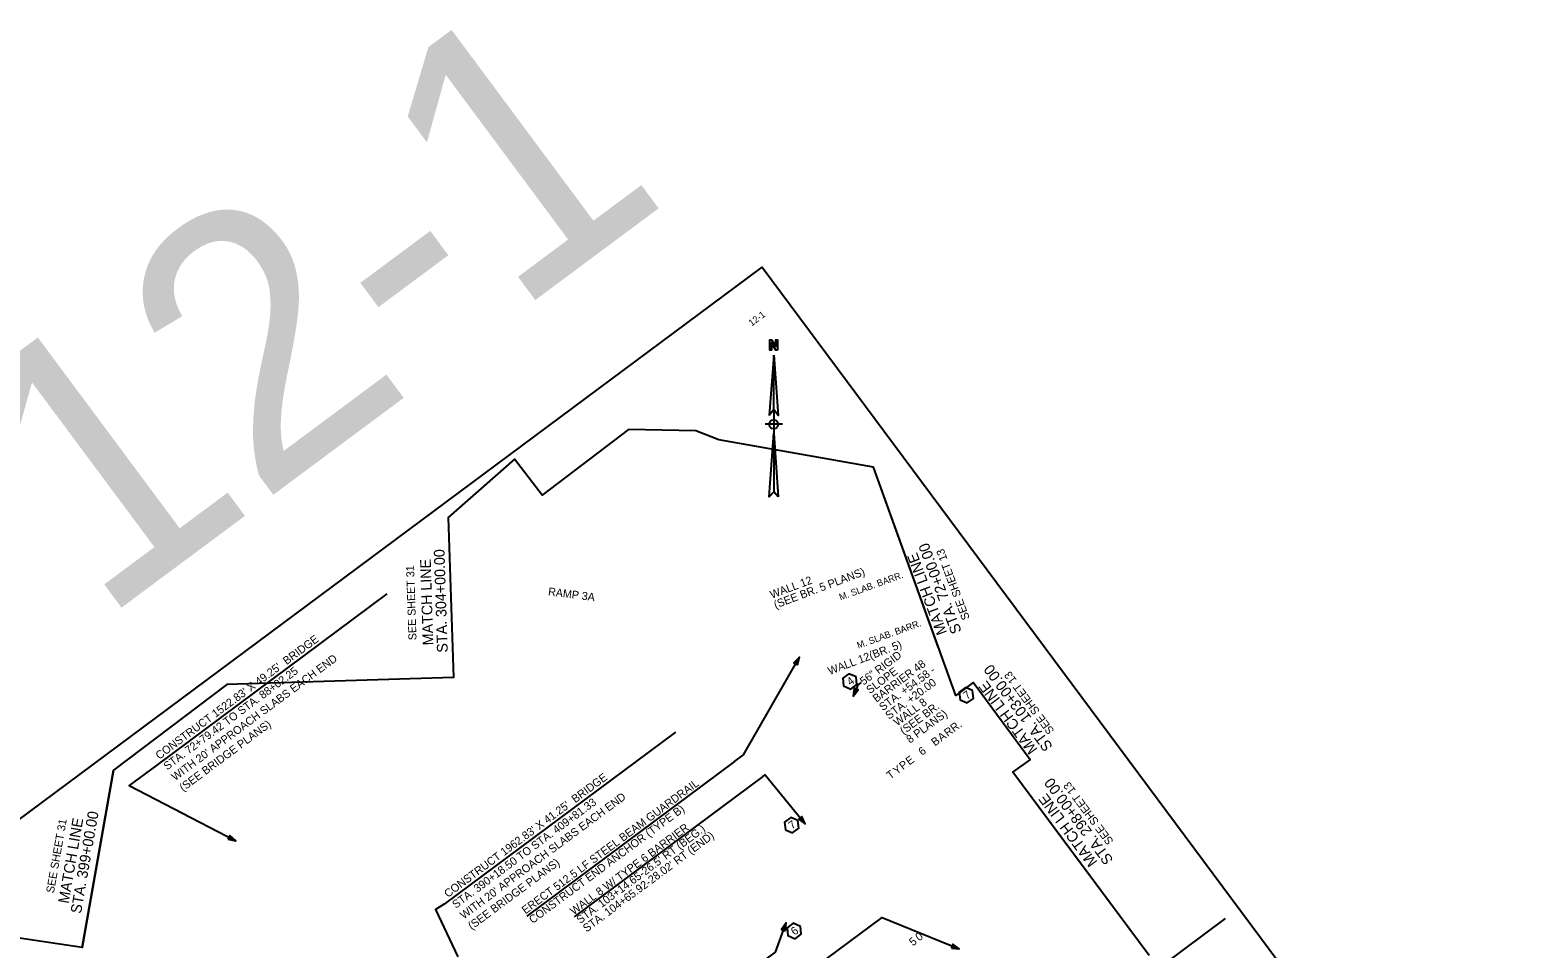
# Model space of a CAD drawing. Extents: x 1609621 to 1611756, y 1093008 to 1094970.
# Drawn here: x 1610636 to 1611756, y 1094282 to 1094970 of the extents above; entities that cross this region are included whole.
import ezdxf

# ---------------------------------------------------------------- set-up
doc = ezdxf.new("R2010")
doc.units = 0
for name, color, linetype in [('Level 1', 7, 'Continuous'), ('Level 2', 7, 'Continuous'), ('Plan_Clip', 7, 'Continuous'), ('RD_PD_GR_TX', 7, 'Continuous'), ('RD_SHT_MatchLine', 7, 'Continuous'), ('RD_SHT_Misc1', 7, 'Continuous'), ('RD_SHT_TX', 7, 'Continuous'), ('RD_TX_Bridge', 7, 'Continuous'), ('RD_TX_RoadID', 7, 'Continuous')]:
    doc.layers.add(name, color=color, linetype=linetype)

msp = doc.modelspace()

# ---------------------------------------------------------------- linework, layer by layer
at = {"layer": 'Level 1'}
for p, q in [((1611193.9, 1094726.3), (1611190.5, 1094681)), ((1611193.9, 1094685.6), (1611190.5, 1094681)), ((1611193.9, 1094685.6), (1611193.9, 1094667.8)), ((1611200.4, 1094674.4), (1611187.4, 1094674.4)), ((1611193.9, 1094667.8), (1611197.3, 1094620)), ((1611197.3, 1094620), (1611193.9, 1094623.8))]:
    msp.add_line(p, q, dxfattribs=at)
msp.add_lwpolyline([(1611196.8, 1094730.1), (1611195.6, 1094730.1), (1611192.2, 1094735.6), (1611192.2, 1094734.8), (1611192.2, 1094730.1), (1611190.9, 1094730.1), (1611190.9, 1094737.7), (1611192.2, 1094737.7), (1611195.6, 1094732.7), (1611195.6, 1094733.1), (1611195.6, 1094737.7), (1611196.8, 1094737.7), (1611196.8, 1094730.1)], dxfattribs=at)
for points in [[(1611193.9, 1094726.3), (1611197.3, 1094681), (1611193.9, 1094685.6)], [(1611193.9, 1094667.8), (1611193.9, 1094623.8), (1611190.5, 1094620)]]:
    msp.add_lwpolyline(points, close=True, dxfattribs=at)
msp.add_circle((1611193.9, 1094674.4), 3.45, dxfattribs=at)
at = {"layer": 'Level 2'}
msp.add_lwpolyline([(1609840.9, 1093793), (1611185.2, 1094792.2), (1611755.8, 1094024.6), (1610411.6, 1093025.3)], close=True, dxfattribs=at)
at = {"layer": 'Plan_Clip'}
msp.add_lwpolyline([(1611475.5, 1094276), (1611373.3, 1094413.5), (1611386.3, 1094422.9), (1611343.4, 1094480.7), (1611330.5, 1094471.1), (1611268.7, 1094642.2), (1611152.7, 1094662.8), (1611135.4, 1094669.5), (1611085, 1094670.6), (1611020.3, 1094621.2), (1610999.6, 1094648.3), (1610949.9, 1094604.4), (1610953.9, 1094484.5), (1610783.9, 1094479.2), (1610698.8, 1094415.1), (1610675.5, 1094282.2), (1610541, 1094302.1)], dxfattribs=at)
msp.add_lwpolyline([(1611475.5, 1094276), (1611373.3, 1094413.5), (1611386.3, 1094422.9), (1611343.4, 1094480.7), (1611330.5, 1094471.1), (1611268.7, 1094642.2), (1611152.7, 1094662.8), (1611135.4, 1094669.5), (1611085, 1094670.6), (1611020.3, 1094621.2), (1610999.6, 1094648.3), (1610949.9, 1094604.4), (1610953.9, 1094484.5), (1610783.9, 1094479.2), (1610698.8, 1094415.1), (1610675.5, 1094282.2), (1610541, 1094302.1)], dxfattribs=at)
at = {"layer": 'RD_PD_GR_TX'}
msp.add_line((1611164.4, 1094421.5), (1611008.7, 1094305.7), dxfattribs=at)
msp.add_lwpolyline([(1611164.4, 1094421.5), (1611171.3, 1094426.6), (1611213.2, 1094499.8)], dxfattribs=at)
msp.add_lwpolyline([(1611211.7, 1094494), (1611213.2, 1094499.8), (1611209, 1094495.6)], close=True, dxfattribs=at)
at = {"layer": 'RD_SHT_MatchLine'}
for p, q in [((1611317.5, 1094506.9), (1611268.7, 1094642.2)), ((1610949.9, 1094604.4), (1610953.9, 1094484.5)), ((1610675.5, 1094282.2), (1610698.8, 1094415.1))]:
    msp.add_line(p, q, dxfattribs=at)
for points in [[(1611386.3, 1094422.9), (1611343.4, 1094480.7)], [(1611475.5, 1094276), (1611410.8, 1094363.1), (1611373.3, 1094413.5)]]:
    msp.add_lwpolyline(points, dxfattribs=at)
at = {"layer": 'RD_SHT_TX'}
for p, q in [((1611185.7, 1094410.3), (1611044.4, 1094305.2)), ((1611532.4, 1094303.8), (1611430.1, 1094227.7))]:
    msp.add_line(p, q, dxfattribs=at)
for points in [[(1611255.7, 1094485.1), (1611250.3, 1094487.4), (1611245.7, 1094484), (1611246.3, 1094478.2), (1611251.7, 1094475.9), (1611256.3, 1094479.4)], [(1611254.3, 1094476.5), (1611253.5, 1094470.5), (1611257.2, 1094475.2)], [(1611343, 1094474.7), (1611337.7, 1094477), (1611333, 1094473.5), (1611333.7, 1094467.8), (1611339, 1094465.5), (1611343.7, 1094468.9)], [(1611212, 1094377.4), (1611206.7, 1094379.7), (1611202, 1094376.2), (1611202.7, 1094370.4), (1611208, 1094368.1), (1611212.7, 1094371.6)], [(1611212.6, 1094378.4), (1611217.5, 1094374.9), (1611215, 1094380.3)], [(1611202.7, 1094294.7), (1611203.2, 1094300.7), (1611199.8, 1094295.7)], [(1611213.9, 1094297.9), (1611208.6, 1094300.3), (1611203.9, 1094296.8), (1611204.6, 1094291), (1611209.9, 1094288.7), (1611214.6, 1094292.2)]]:
    msp.add_lwpolyline(points, close=True, dxfattribs=at)
for points in [[(1611259.5, 1094480.8), (1611257.1, 1094479.1), (1611253.5, 1094470.5)], [(1611185.7, 1094410.3), (1611187.4, 1094411.5), (1611217.5, 1094374.9)], [(1611187.4, 1094272.8), (1611195.3, 1094278.7), (1611203.2, 1094300.7)]]:
    msp.add_lwpolyline(points, dxfattribs=at)
at = {"layer": 'RD_TX_Bridge'}
for p, q in [((1610903.8, 1094547.2), (1610730.3, 1094418.2)), ((1611120.2, 1094443.5), (1610946.8, 1094314.6))]:
    msp.add_line(p, q, dxfattribs=at)
for points in [[(1610730.3, 1094418.2), (1610710.6, 1094403.5), (1610790.5, 1094362.1)], [(1610946.8, 1094314.6), (1610940.4, 1094310.5), (1610957.1, 1094275.1)], [(1611109.4, 1094181.4), (1611275.2, 1094304.6), (1611333, 1094281)]]:
    msp.add_lwpolyline(points, dxfattribs=at)
for points in [[(1610784.7, 1094363.4), (1610790.5, 1094362.1), (1610786.1, 1094366.1)], [(1611327.1, 1094281.7), (1611333, 1094281), (1611328.3, 1094284.6)]]:
    msp.add_lwpolyline(points, close=True, dxfattribs=at)

# ---------------------------------------------------------------- texts
at = {"layer": 'RD_PD_GR_TX'}
for s, p in [('ERECT 512.5 LF STEEL BEAM GUARDRAIL', (1611007.8, 1094306.9)), ('CONSTRUCT END ANCHOR (TYPE B)', (1611013.2, 1094299.7))]:
    msp.add_text(s, height=6, rotation=36.6272, dxfattribs=at).set_placement(p)
at = {"layer": 'RD_SHT_MatchLine'}
for s, height, rotation, p in [('STA. 304+00.00', 8, 91.8205, (1610949.5, 1094503.3)), ('MATCH LINE', 8, 110.5872, (1611324, 1094518.2)), ('STA. 72+00.00', 8, 110.5872, (1611334.9, 1094519.1)), ('SEE SHEET 13', 6, 110.6385, (1611341, 1094529)), ('SEE SHEET 31', 6, 91.912, (1610926.1, 1094512.6)), ('MATCH LINE', 8, 91.8205, (1610938.8, 1094508.8)), ('STA. 103+00.00', 8, 126.6256, (1611403.5, 1094432.9)), ('SEE SHEET 13', 6, 126.6256, (1611404.6, 1094444.7)), ('MATCH LINE', 8, 126.6256, (1611392.1, 1094430.7)), ('STA. 298+00.00', 8, 126.6256, (1611448.9, 1094347.9)), ('MATCH LINE', 8, 126.6256, (1611437, 1094346.3)), ('SEE SHEET 13', 6, 126.6769, (1611449, 1094361.9)), ('SEE SHEET 31', 6, 80.0684, (1610654.2, 1094322.6)), ('MATCH LINE', 8, 80.1395, (1610665.2, 1094314.7)), ('STA. 399+00.00', 8, 80.1395, (1610674.5, 1094307.1))]:
    msp.add_text(s, height=height, rotation=rotation, dxfattribs=at).set_placement(p)
at = {"layer": 'RD_SHT_Misc1'}
msp.add_text('SHEET 12-1', height=200, rotation=36.6256, dxfattribs=at).set_placement((1609913.3, 1093948.5))
at = {"layer": 'RD_SHT_TX'}
for s, height, rotation, p in [('12-1', 5, 36.6256, (1611177.4, 1094747.7)), ('(SEE BR. 5 PLANS)', 6, 20.6215, (1611195.3, 1094536.1)), ('WALL 12', 6, 20.6215, (1611192.5, 1094543.6)), ('M. SLAB. BARR.', 5, 19.8521, (1611244, 1094542.3)), ('M. SLAB. BARR.', 5, 19.8521, (1611257.4, 1094506.1)), ('WALL 12(BR. 5)', 6, 20.6215, (1611235.9, 1094486.4)), ('56" RIGID', 6, 36.6256, (1611261.3, 1094478.5)), ('BARRIER 48', 6, 36.6256, (1611270.9, 1094465.6)), ('SLOPE ', 6, 36.6256, (1611266.1, 1094472)), ('STA. +54.58 -', 6, 36.6256, (1611275.7, 1094459.2)), ('4', 6, 36.6256, (1611251.4, 1094478.2)), ('STA. +20.00', 6, 36.6256, (1611280.4, 1094452.8)), ('WALL 8', 6, 36.6256, (1611286.5, 1094447.8)), ('(SEE BR. ', 6, 36.6256, (1611291.3, 1094441.4)), ('7', 6, 36.6256, (1611338.8, 1094467.8)), ('8 PLANS)', 6, 36.6256, (1611296.1, 1094434.9)), ('A', 6, 36.6256, (1611319.6, 1094436.3)), ('R', 6, 36.6256, (1611324.4, 1094439.9)), ('R', 6, 36.6256, (1611329.1, 1094443.4)), ('.', 6, 36.6256, (1611333.9, 1094447)), ('6', 6, 36.6256, (1611305.2, 1094425.7)), ('B', 6, 36.6256, (1611314.8, 1094432.8)), ('Y', 6, 36.6256, (1611286.1, 1094411.4)), ('P', 6, 36.6256, (1611290.8, 1094415)), ('E', 6, 36.6256, (1611295.6, 1094418.5)), ('T', 6, 36.6256, (1611281.3, 1094407.9)), ('WALL 8 W/ TYPE 6 BARRIER', 6, 36.6256, (1611044, 1094306.2)), ('7', 6, 36.6256, (1611207.7, 1094370.4)), ("STA. 103+14.65-26.5' RT (BEG.)", 6, 36.6256, (1611048.8, 1094299.7)), ("STA. 104+65.92-28.02' RT (END)", 6, 36.6256, (1611053.6, 1094293.3)), ('6', 6, 36.6256, (1611209.5, 1094290.9)), ('5', 6, 38.0577, (1611298.3, 1094282.9)), ('0', 6, 38.0577, (1611303, 1094286.6))]:
    msp.add_text(s, height=height, rotation=rotation, dxfattribs=at).set_placement(p)
at = {"layer": 'RD_TX_Bridge'}
for s, p in [("CONSTRUCT 1522.83' X 49.25'  BRIDGE", (1610733.2, 1094422.8)), ("WITH 20' APPROACH SLABS EACH END", (1610745.1, 1094406.8)), ('STA. 72+79.42 TO STA. 88+02.25', (1610739.1, 1094414.8)), ('(SEE BRIDGE PLANS)', (1610751.1, 1094398.8)), ("CONSTRUCT 1962.83' X 41.25'  BRIDGE", (1610949.6, 1094319.2)), ("WITH 20' APPROACH SLABS EACH END", (1610961.5, 1094303.1)), ('STA. 390+18.50 TO STA. 409+81.33', (1610955.6, 1094311.1)), ('(SEE BRIDGE PLANS)', (1610967.5, 1094295.1))]:
    msp.add_text(s, height=6, rotation=36.6288, dxfattribs=at).set_placement(p)
at = {"layer": 'RD_TX_RoadID'}
msp.add_text('RAMP 3A', height=6, rotation=352.702, dxfattribs=at).set_placement((1611024.5, 1094546.2))

doc.saveas('drawing.dxf')
